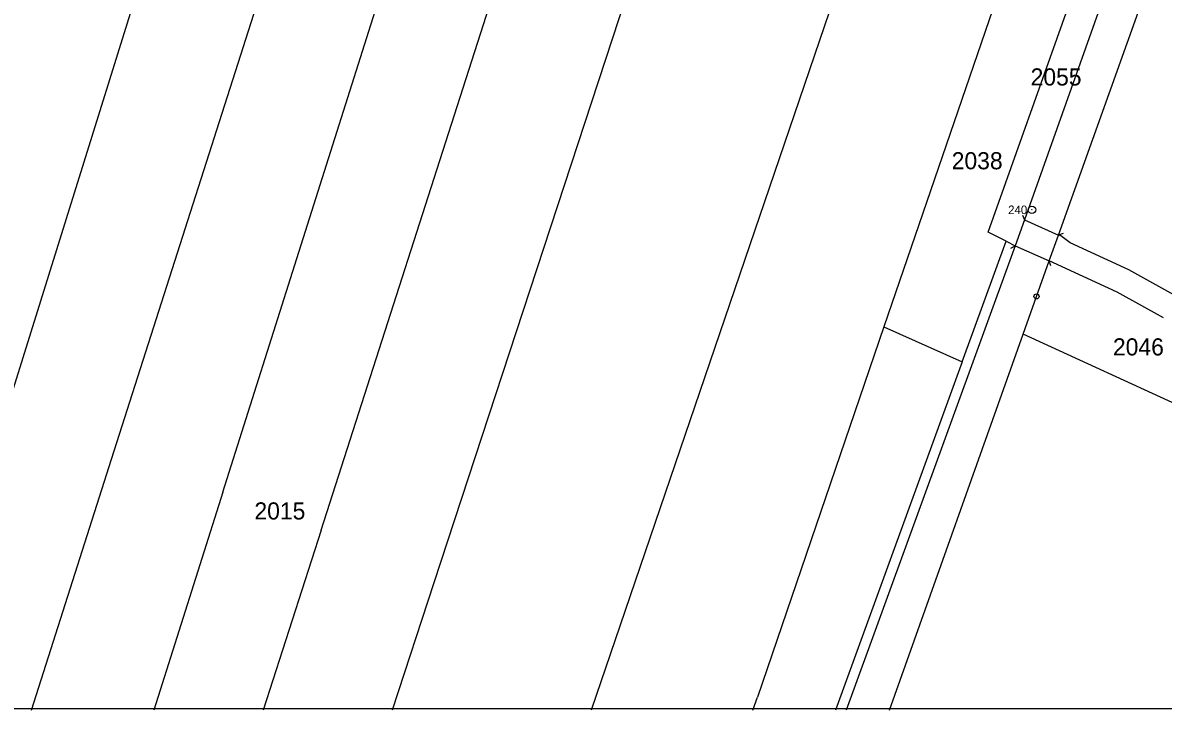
# Model space of a CAD drawing. Extents: x -566461 to -565198, y -1096301 to -1095707.
# Drawn here: x -565912.3 to -565685.9, y -1096301.3 to -1096164.7 of the extents above; entities that cross this region are included whole.
import ezdxf

# ---------------------------------------------------------------- set-up
doc = ezdxf.new("R2010")
doc.units = 0
for name, color, linetype in [('Vrstva 1', 7, 'Continuous'), ('Vrstva 17', 7, 'Continuous'), ('Vrstva 18', 7, 'Continuous'), ('Vrstva 24', 7, 'Continuous'), ('Vrstva 26', 7, 'Continuous'), ('Vrstva 4', 7, 'Continuous'), ('Vrstva 63', 7, 'Continuous')]:
    doc.layers.add(name, color=color, linetype=linetype)

msp = doc.modelspace()

# ---------------------------------------------------------------- linework, layer by layer
at = {"layer": 'Vrstva 1'}
for p, q in [((-565876.67, -1096116.85), (-565915.86, -1096242.54)), ((-565894.7, -1096251.46), (-565853.27, -1096121.84)), ((-565872.6, -1096257.97), (-565830.85, -1096126.18)), ((-565853.1, -1096265.52), (-565809.72, -1096130.27)), ((-565706.66, -1096206.91), (-565678.86, -1096129.12)), ((-565785.01, -1096136.58), (-565830.71, -1096276)), ((-565746.3, -1096145.21), (-565794.69, -1096287.35)), ((-565693.35, -1096147.49), (-565713.41, -1096203.88)), ((-565715.49, -1096149.63), (-565741.31, -1096225.16)), ((-565720.65, -1096206.33), (-565704.82, -1096161.83)), ((-565713.41, -1096203.88), (-565715.24, -1096209.02)), ((-565717.05, -1096208.12), (-565720.65, -1096206.33)), ((-565708.49, -1096212.04), (-565706.66, -1096206.91)), ((-565706.19, -1096207.05), (-565706.66, -1096206.91)), ((-565704.33, -1096208.45), (-565706.19, -1096207.05)), ((-565715.24, -1096209.02), (-565748.81, -1096301.3)), ((-565725.77, -1096232.1), (-565717.05, -1096208.12)), ((-565717.05, -1096208.12), (-565715.24, -1096209.02)), ((-565692.71, -1096213.82), (-565704.33, -1096208.45)), ((-565711.02, -1096219.1), (-565708.49, -1096212.04)), ((-565694.97, -1096218.28), (-565708.49, -1096212.04)), ((-565683.18, -1096219.08), (-565692.71, -1096213.82)), ((-565713.68, -1096226.59), (-565711.02, -1096219.1)), ((-565685.8, -1096223.34), (-565694.97, -1096218.28)), ((-565741.31, -1096225.16), (-565766.45, -1096298.7)), ((-565741.31, -1096225.16), (-565725.77, -1096232.1)), ((-565740.22, -1096301.3), (-565713.68, -1096226.59)), ((-565666.06, -1096248.46), (-565713.68, -1096226.59)), ((-565725.77, -1096232.1), (-565750.94, -1096301.3)), ((-565910.63, -1096301.3), (-565894.7, -1096251.46)), ((-565872.6, -1096257.97), (-565886.33, -1096301.3)), ((-565853.1, -1096265.52), (-565864.58, -1096301.3)), ((-565830.71, -1096276), (-565839, -1096301.3)), ((-565794.69, -1096287.35), (-565799.44, -1096301.3)), ((-565767.34, -1096301.3), (-565766.45, -1096298.7))]:
    msp.add_line(p, q, dxfattribs=at)
at = {"layer": 'Vrstva 24'}
for centre, radius in [((-565711.93, -1096201.89), 0.75), ((-565711.93, -1096201.89), 0.0327), ((-565711.02, -1096219.1), 0.5), ((-565711.02, -1096219.1), 0.0327)]:
    msp.add_circle(centre, radius, dxfattribs=at)
at = {"layer": 'Vrstva 26'}
for p, q in [((-565713.81, -1096202.97), (-565713.41, -1096203.88)), ((-565705.7, -1096206.62), (-565706.66, -1096206.91)), ((-565716.11, -1096209.51), (-565715.24, -1096209.02)), ((-565708.18, -1096212.99), (-565708.49, -1096212.04))]:
    msp.add_line(p, q, dxfattribs=at)
at = {"layer": 'Vrstva 4'}
for p, q in [((-565713.41, -1096203.88), (-565706.66, -1096206.91)), ((-565715.24, -1096209.02), (-565708.49, -1096212.04))]:
    msp.add_line(p, q, dxfattribs=at)
at = {"layer": 'Vrstva 63'}
msp.add_line((-565198.38, -1096301.03), (-566458.38, -1096301.03), dxfattribs=at)

# ---------------------------------------------------------------- texts
at = {"layer": 'Vrstva 17'}
msp.add_text('240', height=1.7, dxfattribs=at).set_placement((-565716.65, -1096202.74))
at = {"layer": 'Vrstva 18'}
for s, p in [('2055', (-565712.19, -1096177.19)), ('2038', (-565727.86, -1096193.84)), ('2046', (-565695.84, -1096230.82)), ('2015', (-565866.33, -1096263.41))]:
    msp.add_text(s, height=3.4, dxfattribs=at).set_placement(p)

doc.saveas('drawing.dxf')
